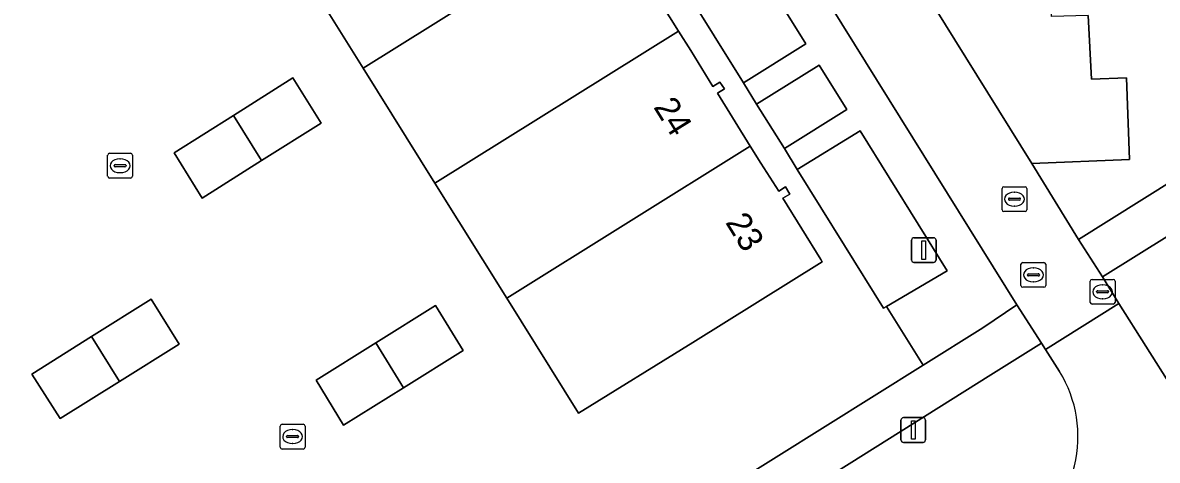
# Model space of a CAD drawing. Extents: x 159279 to 160377, y 384531 to 385888.
# Drawn here: x 159545.75 to 159591.51, y 385322.46 to 385340.09 of the extents above; entities that cross this region are included whole.
import ezdxf

# ---------------------------------------------------------------- set-up
doc = ezdxf.new("R2010")
doc.units = 0
for name, color, linetype in [('IMGEO_Berm_groen', 7, 'Continuous'), ('IMGEO_Erf', 7, 'Continuous'), ('IMGEO_Groenvoorziening', 7, 'Continuous'), ('IMGEO_Kolk', 7, 'Continuous'), ('IMGEO_Lichtmast', 7, 'Continuous'), ('IMGEO_Pand', 7, 'Continuous'), ('IMGEO_Pand_nummerreeks', 7, 'Continuous'), ('IMGEO_Parkeervlak_open', 7, 'Continuous'), ('IMGEO_Rijbaan_lokaal_open', 7, 'Continuous'), ('IMGEO_Rioolput', 7, 'Continuous'), ('IMGEO_Voetpad_open', 7, 'Continuous')]:
    doc.layers.add(name, color=color, linetype=linetype)

msp = doc.modelspace()

# ---------------------------------------------------------------- linework, layer by layer
at = {"layer": 'IMGEO_Berm_groen'}
msp.add_lwpolyline([(159587.57, 385326.03), (159586.995, 385326.924), (159586.834, 385327.175), (159584.791, 385325.894), (159573.372, 385318.733), (159558.23, 385297.216), (159551.196, 385287.274), (159548.544, 385283.515)], dxfattribs=at)
msp.add_arc((159583.321, 385323.417), 4.988, 301.0523, 31.5889, dxfattribs=at)
at = {"layer": 'IMGEO_Erf'}
for points in [[(159572.183, 385320.11), (159582.07, 385326.296), (159580.588, 385328.659), (159580.47, 385328.59), (159578.9, 385331.111), (159576.983, 385334.18), (159576.47, 385335.019), (159575.349, 385336.809), (159574.82, 385337.661), (159571.269, 385343.361)], [(159570.686, 385342.179), (159572.201, 385339.751), (159572.691, 385338.966), (159573.585, 385337.522), (159573.866, 385337.689), (159574.053, 385337.419), (159573.77, 385337.244), (159575.095, 385335.117), (159575.52, 385334.435), (159576.239, 385333.304), (159576.517, 385333.472), (159576.683, 385333.182), (159576.406, 385333.018), (159577.943, 385330.542), (159577.995, 385330.458), (159572.775, 385327.2), (159568.164, 385324.35), (159565.271, 385328.984), (159562.378, 385333.618), (159559.485, 385338.252), (159556.592, 385342.886)]]:
    msp.add_lwpolyline(points, dxfattribs=at)
for points in [[(159555.39, 385334.536), (159552.986, 385333.025), (159551.868, 385334.844), (159554.249, 385336.351), (159556.65, 385337.871), (159557.794, 385336.046)], [(159549.664, 385325.637), (159547.266, 385324.136), (159546.124, 385325.931), (159548.533, 385327.444), (159550.936, 385328.952), (159552.062, 385327.138)], [(159558.688, 385323.87), (159557.583, 385325.684), (159559.99, 385327.186), (159562.396, 385328.688), (159563.512, 385326.876), (159561.115, 385325.382)]]:
    msp.add_lwpolyline(points, close=True, dxfattribs=at)
at = {"layer": 'IMGEO_Groenvoorziening'}
for points in [[(159571.269, 385343.361), (159574.82, 385337.661), (159577.34, 385339.237), (159573.793, 385344.911)], [(159575.349, 385336.809), (159576.47, 385335.019), (159578.983, 385336.591), (159577.872, 385338.372)], [(159579.528, 385335.734), (159576.983, 385334.18), (159578.9, 385331.111), (159580.47, 385328.59), (159580.588, 385328.659), (159583.039, 385330.094)]]:
    msp.add_lwpolyline(points, close=True, dxfattribs=at)
for points in [[(159588.719, 385340.384), (159588.853, 385337.815), (159590.27, 385337.874), (159590.384, 385334.581), (159586.447, 385334.412), (159588.331, 385331.359), (159598.867, 385337.949)], [(159603.181, 385332.247), (159601.016, 385335.722), (159600.453, 385336.627), (159600.372, 385336.757), (159589.295, 385329.853), (159589.962, 385328.78), (159592.131, 385325.342)]]:
    msp.add_lwpolyline(points, dxfattribs=at)
at = {"layer": 'IMGEO_Kolk'}
for p, q in [((159549.181, 385333.9), (159549.181, 385334.752)), ((159549.256, 385334.826), (159550.108, 385334.826)), ((159549.669, 385334.606), (159549.694, 385334.606)), ((159550.182, 385334.752), (159550.182, 385333.9)), ((159549.44, 385334.32), (159549.44, 385334.332)), ((159549.878, 385334.283), (159549.48, 385334.283)), ((159549.483, 385334.369), (159549.881, 385334.369)), ((159549.924, 385334.332), (159549.924, 385334.32)), ((159550.108, 385333.826), (159549.256, 385333.826)), ((159549.692, 385334.046), (159549.667, 385334.046)), ((159588.803, 385328.82), (159588.803, 385329.672)), ((159588.878, 385329.746), (159589.73, 385329.746)), ((159589.291, 385329.526), (159589.316, 385329.526)), ((159589.804, 385329.672), (159589.804, 385328.82)), ((159589.062, 385329.24), (159589.062, 385329.252)), ((159589.5, 385329.203), (159589.102, 385329.203)), ((159589.105, 385329.289), (159589.503, 385329.289)), ((159589.546, 385329.252), (159589.546, 385329.24)), ((159589.73, 385328.746), (159588.878, 385328.746)), ((159589.314, 385328.966), (159589.289, 385328.966)), ((159556.138, 385322.985), (159556.138, 385323.837)), ((159556.213, 385323.911), (159557.065, 385323.911)), ((159556.626, 385323.691), (159556.651, 385323.691)), ((159557.139, 385323.837), (159557.139, 385322.985)), ((159556.397, 385323.405), (159556.397, 385323.417)), ((159556.835, 385323.368), (159556.437, 385323.368)), ((159556.44, 385323.454), (159556.838, 385323.454)), ((159556.649, 385323.131), (159556.624, 385323.131)), ((159556.881, 385323.417), (159556.881, 385323.405)), ((159557.065, 385322.911), (159556.213, 385322.911))]:
    msp.add_line(p, q, dxfattribs=at)
for points in [[(159549.181, 385333.9), (159549.181, 385334.752)], [(159549.256, 385334.826), (159550.108, 385334.826)], [(159550.182, 385334.752), (159550.182, 385333.9)], [(159550.108, 385333.826), (159549.256, 385333.826)], [(159588.803, 385328.82), (159588.803, 385329.672)], [(159588.878, 385329.746), (159589.73, 385329.746)], [(159589.804, 385329.672), (159589.804, 385328.82)], [(159589.73, 385328.746), (159588.878, 385328.746)], [(159556.138, 385322.985), (159556.138, 385323.837)], [(159556.213, 385323.911), (159557.065, 385323.911)], [(159557.139, 385323.837), (159557.139, 385322.985)], [(159557.065, 385322.911), (159556.213, 385322.911)]]:
    msp.add_lwpolyline(points, dxfattribs=at)
for centre, radius, start, end in [((159549.258, 385334.75), 0.0765, 91.552, 178.448), ((159549.258, 385334.75), 0.0765, 91.552, 178.448), ((159550.106, 385334.75), 0.0765, 1.552, 88.448), ((159550.106, 385334.75), 0.0765, 1.552, 88.448), ((159549.48, 385334.329), 0.0403, 85.8775, 175.7526), ((159549.477, 385334.319), 0.0366, 178.938, 274.7102), ((159549.881, 385334.326), 0.043, 264.8664, 352.4533), ((159549.885, 385334.331), 0.0386, 1.7309, 96.639), ((159549.258, 385333.902), 0.0765, 181.552, 268.448), ((159549.258, 385333.902), 0.0765, 181.552, 268.448), ((159550.106, 385333.902), 0.0765, 271.552, 358.448), ((159550.106, 385333.902), 0.0765, 271.552, 358.448), ((159588.88, 385329.67), 0.0765, 91.552, 178.448), ((159588.88, 385329.67), 0.0765, 91.552, 178.448), ((159589.728, 385329.67), 0.0765, 1.552, 88.448), ((159589.728, 385329.67), 0.0765, 1.552, 88.448), ((159589.102, 385329.249), 0.0403, 85.8775, 175.7526), ((159589.099, 385329.239), 0.0366, 178.938, 274.7102), ((159589.503, 385329.246), 0.043, 264.8664, 352.4533), ((159589.507, 385329.251), 0.0386, 1.7309, 96.639), ((159588.88, 385328.822), 0.0765, 181.552, 268.448), ((159588.88, 385328.822), 0.0765, 181.552, 268.448), ((159589.728, 385328.822), 0.0765, 271.552, 358.448), ((159589.728, 385328.822), 0.0765, 271.552, 358.448), ((159556.215, 385323.835), 0.0765, 91.552, 178.448), ((159556.215, 385323.835), 0.0765, 91.552, 178.448), ((159557.063, 385323.835), 0.0765, 1.552, 88.448), ((159557.063, 385323.835), 0.0765, 1.552, 88.448), ((159556.437, 385323.414), 0.0403, 85.8775, 175.7526), ((159556.434, 385323.404), 0.0366, 178.938, 274.7102), ((159556.838, 385323.411), 0.043, 264.8664, 352.4533), ((159556.842, 385323.416), 0.0386, 1.7309, 96.639), ((159556.215, 385322.987), 0.0765, 181.552, 268.448), ((159556.215, 385322.987), 0.0765, 181.552, 268.448), ((159557.063, 385322.987), 0.0765, 271.552, 358.448), ((159557.063, 385322.987), 0.0765, 271.552, 358.448)]:
    msp.add_arc(centre, radius, start, end, dxfattribs=at)
for centre, major_axis, ratio, start_param, end_param in [((159549.668, 385334.326), (-0.387, 0.002), 0.722429, 4.712389, 7.853982), ((159549.693, 385334.326), (-0.39, 0.002), 0.717154, 1.570796, 4.712389), ((159589.29, 385329.246), (-0.387, 0.002), 0.722429, 4.712389, 7.853982), ((159589.315, 385329.246), (-0.39, 0.002), 0.717154, 1.570796, 4.712389), ((159556.625, 385323.411), (-0.387, 0.002), 0.722429, 4.712389, 7.853982), ((159556.65, 385323.411), (-0.39, 0.002), 0.717154, 1.570796, 4.712389)]:
    msp.add_ellipse(centre, major_axis=major_axis, ratio=ratio, start_param=start_param, end_param=end_param, dxfattribs=at)
at = {"layer": 'IMGEO_Lichtmast'}
for p, q in [((159581.595, 385330.526), (159581.595, 385331.326)), ((159581.595, 385331.326), (159581.595, 385330.526)), ((159581.695, 385331.426), (159582.485, 385331.426)), ((159582.485, 385331.426), (159581.695, 385331.426)), ((159582.585, 385331.326), (159582.585, 385330.526)), ((159582.585, 385330.526), (159582.585, 385331.326)), ((159582.485, 385330.426), (159581.695, 385330.426)), ((159581.695, 385330.426), (159582.485, 385330.426)), ((159581.17, 385323.276), (159581.17, 385324.076)), ((159581.17, 385324.076), (159581.17, 385323.276)), ((159581.27, 385324.176), (159582.06, 385324.176)), ((159582.06, 385324.176), (159581.27, 385324.176)), ((159582.16, 385324.076), (159582.16, 385323.276)), ((159582.16, 385323.276), (159582.16, 385324.076)), ((159582.06, 385323.176), (159581.27, 385323.176)), ((159581.27, 385323.176), (159582.06, 385323.176))]:
    msp.add_line(p, q, dxfattribs=at)
for points in [[(159582.015, 385331.301), (159582.165, 385331.301), (159582.165, 385330.551), (159582.015, 385330.551), (159582.015, 385331.301)], [(159581.59, 385324.051), (159581.74, 385324.051), (159581.74, 385323.301), (159581.59, 385323.301), (159581.59, 385324.051)]]:
    msp.add_lwpolyline(points, dxfattribs=at)
for centre, start, end in [((159581.695, 385331.326), 90, 180), ((159581.695, 385331.326), 90, 180), ((159582.485, 385331.326), 0, 90), ((159582.485, 385331.326), 360, 90), ((159581.695, 385330.526), 180, 270), ((159581.695, 385330.526), 180, 270), ((159582.485, 385330.526), 270, 0), ((159582.485, 385330.526), 270, 0), ((159581.27, 385324.076), 90, 180), ((159581.27, 385324.076), 90, 180), ((159582.06, 385324.076), 0, 90), ((159582.06, 385324.076), 360, 90), ((159581.27, 385323.276), 180, 270), ((159581.27, 385323.276), 180, 270), ((159582.06, 385323.276), 270, 0), ((159582.06, 385323.276), 270, 0)]:
    msp.add_arc(centre, 0.1, start, end, dxfattribs=at)
at = {"layer": 'IMGEO_Pand'}
for points in [[(159569.314, 385344.389), (159568.051, 385346.406), (159568.329, 385346.58), (159568.16, 385346.854), (159567.875, 385346.687), (159566.422, 385349.023), (159556.592, 385342.886), (159559.485, 385338.252)], [(159572.201, 385339.751), (159570.686, 385342.179), (159570.971, 385342.344), (159570.797, 385342.635), (159570.516, 385342.469), (159569.314, 385344.389), (159559.485, 385338.252), (159562.378, 385333.618)], [(159575.095, 385335.117), (159573.77, 385337.244), (159574.053, 385337.419), (159573.866, 385337.689), (159573.585, 385337.522), (159572.691, 385338.966), (159572.201, 385339.751), (159562.378, 385333.618), (159565.271, 385328.984)], [(159554.249, 385336.351), (159555.39, 385334.536), (159557.794, 385336.046), (159556.65, 385337.871)], [(159554.249, 385336.351), (159551.868, 385334.844), (159552.986, 385333.025), (159555.39, 385334.536)], [(159577.943, 385330.542), (159576.406, 385333.018), (159576.683, 385333.182), (159576.517, 385333.472), (159576.239, 385333.304), (159575.52, 385334.435), (159575.095, 385335.117), (159565.271, 385328.984), (159568.164, 385324.35), (159572.775, 385327.2), (159577.995, 385330.458)], [(159548.533, 385327.444), (159549.664, 385325.637), (159552.062, 385327.138), (159550.936, 385328.952)], [(159562.396, 385328.688), (159559.99, 385327.186), (159561.115, 385325.382), (159563.512, 385326.876)], [(159548.533, 385327.444), (159546.124, 385325.931), (159547.266, 385324.136), (159549.664, 385325.637)], [(159561.115, 385325.382), (159559.99, 385327.186), (159557.583, 385325.684), (159558.688, 385323.87)]]:
    msp.add_lwpolyline(points, close=True, dxfattribs=at)
at = {"layer": 'IMGEO_Parkeervlak_open'}
msp.add_lwpolyline([(159579.858, 385344.998), (159586.447, 385334.412), (159590.384, 385334.581), (159590.27, 385337.874), (159588.853, 385337.815), (159588.719, 385340.384), (159587.243, 385340.341), (159587.154, 385342.898), (159585.799, 385342.872), (159585.722, 385345.201)], close=True, dxfattribs=at)
at = {"layer": 'IMGEO_Rijbaan_lokaal_open'}
for points in [[(159566.721, 385396.176), (159543.163, 385433.937), (159526.721, 385423.666), (159557.684, 385373.918), (159585.844, 385328.715), (159586.834, 385327.175), (159586.995, 385326.924), (159589.962, 385328.78), (159589.295, 385329.853), (159588.331, 385331.359), (159586.447, 385334.412), (159579.858, 385344.998), (159579.015, 385346.375), (159573.978, 385354.409), (159573.199, 385355.697), (159568.168, 385363.744), (159567.323, 385365.147), (159562.201, 385373.298), (159561.027, 385375.175)], [(159592.131, 385325.342), (159589.962, 385328.78), (159586.995, 385326.924), (159587.57, 385326.03)]]:
    msp.add_lwpolyline(points, dxfattribs=at)
msp.add_arc((159583.321, 385323.417), 4.988, 301.0523, 31.5889, dxfattribs=at)
at = {"layer": 'IMGEO_Rioolput'}
for p, q in [((159585.246, 385332.553), (159585.246, 385333.405)), ((159585.321, 385333.479), (159586.173, 385333.479)), ((159585.734, 385333.259), (159585.759, 385333.259)), ((159586.247, 385333.405), (159586.247, 385332.553)), ((159585.505, 385332.973), (159585.505, 385332.985)), ((159585.943, 385332.936), (159585.545, 385332.936)), ((159585.548, 385333.022), (159585.946, 385333.022)), ((159585.757, 385332.699), (159585.732, 385332.699)), ((159585.989, 385332.985), (159585.989, 385332.973)), ((159586.173, 385332.479), (159585.321, 385332.479)), ((159586.085, 385330.428), (159586.937, 385330.428)), ((159586.01, 385329.502), (159586.01, 385330.354)), ((159586.312, 385329.971), (159586.71, 385329.971)), ((159586.498, 385330.208), (159586.523, 385330.208)), ((159587.011, 385330.354), (159587.011, 385329.502)), ((159586.269, 385329.922), (159586.269, 385329.934)), ((159586.707, 385329.885), (159586.309, 385329.885)), ((159586.521, 385329.648), (159586.496, 385329.648)), ((159586.753, 385329.934), (159586.753, 385329.922)), ((159586.937, 385329.428), (159586.085, 385329.428))]:
    msp.add_line(p, q, dxfattribs=at)
for points in [[(159585.246, 385332.553), (159585.246, 385333.405)], [(159585.321, 385333.479), (159586.173, 385333.479)], [(159586.247, 385333.405), (159586.247, 385332.553)], [(159586.173, 385332.479), (159585.321, 385332.479)], [(159586.085, 385330.428), (159586.937, 385330.428)], [(159586.01, 385329.502), (159586.01, 385330.354)], [(159587.011, 385330.354), (159587.011, 385329.502)], [(159586.937, 385329.428), (159586.085, 385329.428)]]:
    msp.add_lwpolyline(points, dxfattribs=at)
for centre, radius, start, end in [((159585.323, 385333.403), 0.0765, 91.552, 178.448), ((159585.323, 385333.403), 0.0765, 91.552, 178.448), ((159586.171, 385333.403), 0.0765, 1.552, 88.448), ((159586.171, 385333.403), 0.0765, 1.552, 88.448), ((159585.545, 385332.982), 0.0403, 85.8775, 175.7526), ((159585.542, 385332.972), 0.0366, 178.938, 274.7102), ((159585.946, 385332.979), 0.043, 264.8664, 352.4533), ((159585.95, 385332.984), 0.0386, 1.7309, 96.639), ((159585.323, 385332.555), 0.0765, 181.552, 268.448), ((159585.323, 385332.555), 0.0765, 181.552, 268.448), ((159586.171, 385332.555), 0.0765, 271.552, 358.448), ((159586.171, 385332.555), 0.0765, 271.552, 358.448), ((159586.087, 385330.352), 0.0765, 91.552, 178.448), ((159586.087, 385330.352), 0.0765, 91.552, 178.448), ((159586.935, 385330.352), 0.0765, 1.552, 88.448), ((159586.935, 385330.352), 0.0765, 1.552, 88.448), ((159586.309, 385329.931), 0.0403, 85.8775, 175.7526), ((159586.714, 385329.933), 0.0386, 1.7309, 96.639), ((159586.087, 385329.504), 0.0765, 181.552, 268.448), ((159586.087, 385329.504), 0.0765, 181.552, 268.448), ((159586.306, 385329.921), 0.0366, 178.938, 274.7102), ((159586.71, 385329.928), 0.043, 264.8664, 352.4533), ((159586.935, 385329.504), 0.0765, 271.552, 358.448), ((159586.935, 385329.504), 0.0765, 271.552, 358.448)]:
    msp.add_arc(centre, radius, start, end, dxfattribs=at)
for centre, major_axis, ratio, start_param, end_param in [((159585.733, 385332.979), (-0.387, 0.002), 0.722429, 4.712389, 7.853982), ((159585.758, 385332.979), (-0.39, 0.002), 0.717154, 1.570796, 4.712389), ((159586.497, 385329.928), (-0.387, 0.002), 0.722429, 4.712389, 7.853982), ((159586.522, 385329.928), (-0.39, 0.002), 0.717154, 1.570796, 4.712389)]:
    msp.add_ellipse(centre, major_axis=major_axis, ratio=ratio, start_param=start_param, end_param=end_param, dxfattribs=at)
at = {"layer": 'IMGEO_Voetpad_open'}
for points in [[(159573.793, 385344.911), (159577.34, 385339.237), (159574.82, 385337.661), (159575.349, 385336.809), (159577.872, 385338.372), (159578.983, 385336.591), (159576.47, 385335.019), (159576.983, 385334.18), (159579.528, 385335.734), (159583.039, 385330.094), (159580.588, 385328.659), (159582.07, 385326.296), (159584.469, 385327.797), (159585.844, 385328.715), (159557.684, 385373.918)], [(159558.23, 385297.216), (159573.372, 385318.733), (159584.791, 385325.894), (159586.834, 385327.175), (159585.844, 385328.715), (159584.469, 385327.797), (159582.07, 385326.296), (159572.183, 385320.11), (159549.295, 385287.709), (159548.078, 385286.038), (159547.47, 385285.17), (159548.124, 385284.071)]]:
    msp.add_lwpolyline(points, dxfattribs=at)
msp.add_lwpolyline([(159600.372, 385336.757), (159599.289, 385338.209), (159598.867, 385337.949), (159588.331, 385331.359), (159589.295, 385329.853)], close=True, dxfattribs=at)

# ---------------------------------------------------------------- texts
at = {"layer": 'IMGEO_Pand_nummerreeks'}
for s, rotation, p in [('24', 301.925, (159571.169, 385336.691)), ('23', 301.8276, (159574.069, 385332.043))]:
    msp.add_text(s, height=1, rotation=rotation, dxfattribs=at).set_placement(p)

doc.saveas('drawing.dxf')
